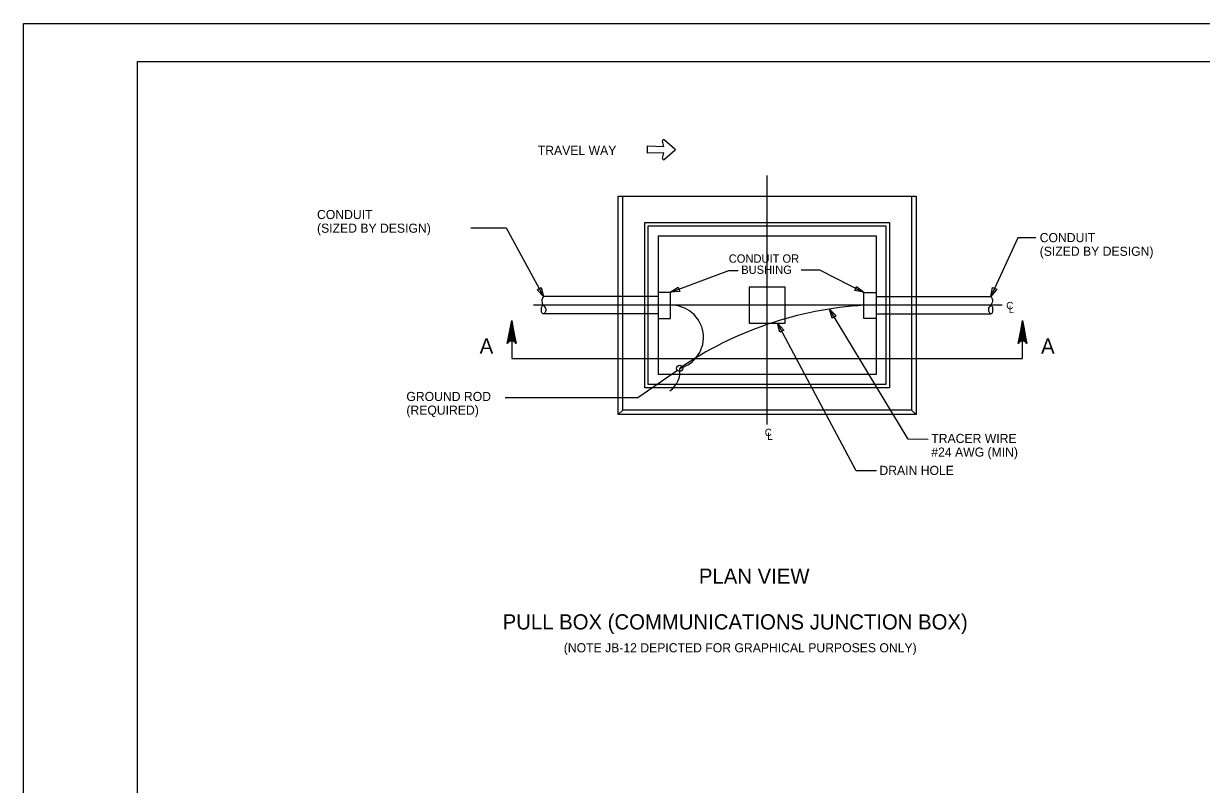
# Model space of a CAD drawing. Extents: x 1299104.8 to 1299141.6, y 239639.8 to 239661.8.
# Drawn here: x 1299104.8 to 1299120.31, y 239651.78 to 239661.8 of the extents above; entities that cross this region are included whole.
import ezdxf

# ---------------------------------------------------------------- set-up
doc = ezdxf.new("R2010")
doc.units = 0
for name, color, linetype in [('DIM TXT', 7, 'Continuous'), ('GS_plotshape_p', 7, 'Continuous'), ('Level 1', 7, 'Continuous'), ('PDF4_Geometry', 7, 'Continuous'), ('PDF4_Solid Fills', 7, 'Continuous')]:
    doc.layers.add(name, color=color, linetype=linetype)

msp = doc.modelspace()

# ---------------------------------------------------------------- linework, layer by layer
at = {"layer": 'DIM TXT'}
for p, q in [((1299113.015, 239660.092), (1299113.015, 239660.188)), ((1299113.015, 239660.188), (1299113.232, 239660.181)), ((1299113.232, 239660.181), (1299113.213, 239660.253)), ((1299113.213, 239660.253), (1299113.213, 239660.253)), ((1299113.238, 239660.269), (1299113.377, 239660.152)), ((1299113.232, 239660.099), (1299113.015, 239660.092)), ((1299113.213, 239660.027), (1299113.232, 239660.099)), ((1299113.377, 239660.128), (1299113.238, 239660.011)), ((1299114.59, 239656.519), (1299114.59, 239659.799)), ((1299112.63, 239656.65), (1299112.63, 239659.529)), ((1299112.63, 239659.529), (1299116.55, 239659.529)), ((1299116.55, 239659.529), (1299116.55, 239656.65)), ((1299112.981, 239657.001), (1299112.981, 239659.178)), ((1299112.981, 239659.178), (1299116.199, 239659.178)), ((1299113.023, 239657.045), (1299113.023, 239659.134)), ((1299113.023, 239659.134), (1299116.153, 239659.134)), ((1299116.153, 239659.134), (1299116.153, 239657.045)), ((1299116.199, 239659.178), (1299116.199, 239657.001)), ((1299113.156, 239659.003), (1299116.024, 239659.003)), ((1299113.156, 239659.003), (1299113.156, 239657.176)), ((1299116.024, 239659.003), (1299116.024, 239657.176)), ((1299114.08, 239658.545), (1299113.316, 239658.257)), ((1299114.208, 239658.545), (1299114.08, 239658.545)), ((1299115.286, 239658.551), (1299115.038, 239658.551)), ((1299115.286, 239658.551), (1299115.865, 239658.257)), ((1299112.63, 239658.203), (1299111.645, 239658.203)), ((1299113.156, 239658.203), (1299112.63, 239658.203)), ((1299113.316, 239658.257), (1299113.156, 239658.257)), ((1299113.316, 239657.917), (1299113.316, 239658.257)), ((1299115.865, 239658.257), (1299116.024, 239658.257)), ((1299115.865, 239657.917), (1299115.865, 239658.257)), ((1299116.024, 239658.203), (1299116.55, 239658.203)), ((1299116.55, 239658.203), (1299117.535, 239658.203)), ((1299117.686, 239658.089), (1299111.513, 239658.089)), ((1299112.63, 239657.976), (1299111.645, 239657.976)), ((1299113.156, 239657.976), (1299112.63, 239657.976)), ((1299116.445, 239656.324), (1299115.41, 239658.04)), ((1299116.024, 239657.976), (1299116.55, 239657.976)), ((1299116.55, 239657.976), (1299117.535, 239657.976)), ((1299113.156, 239657.917), (1299113.316, 239657.917)), ((1299115.762, 239655.908), (1299114.727, 239657.855)), ((1299116.024, 239657.917), (1299115.865, 239657.917)), ((1299115.895, 239657.259), (1299115.894, 239657.26)), ((1299116.153, 239657.045), (1299113.023, 239657.045)), ((1299116.199, 239657.001), (1299112.981, 239657.001)), ((1299112.689, 239656.709), (1299112.63, 239656.65)), ((1299116.55, 239656.65), (1299112.63, 239656.65)), ((1299116.133, 239656.709), (1299112.689, 239656.709)), ((1299116.492, 239656.709), (1299116.133, 239656.709)), ((1299116.492, 239656.709), (1299116.55, 239656.65)), ((1299116.712, 239656.323), (1299116.445, 239656.324)), ((1299116.029, 239655.907), (1299115.762, 239655.908))]:
    msp.add_line(p, q, dxfattribs=at)
for points in [[(1299112.689, 239656.709), (1299112.689, 239659.529)], [(1299116.492, 239659.529), (1299116.492, 239656.709)], [(1299110.689, 239659.111), (1299111.156, 239659.111), (1299111.645, 239658.203)], [(1299118.129, 239658.979), (1299117.889, 239658.979), (1299117.535, 239658.203)], [(1299111.142, 239656.876), (1299112.886, 239656.876), (1299113.408, 239657.233)], [(1299116.024, 239657.176), (1299113.156, 239657.176)]]:
    msp.add_lwpolyline(points, dxfattribs=at)
for points in [[(1299111.614, 239658.323), (1299111.645, 239658.203), (1299111.561, 239658.293)], [(1299113.439, 239658.269), (1299113.315, 239658.26), (1299113.42, 239658.326)], [(1299114.827, 239657.853), (1299114.827, 239658.326), (1299114.354, 239658.326), (1299114.354, 239657.853)], [(1299115.768, 239658.337), (1299115.864, 239658.26), (1299115.743, 239658.283)], [(1299117.612, 239658.3), (1299117.535, 239658.203), (1299117.557, 239658.325)], [(1299115.446, 239657.921), (1299115.41, 239658.04), (1299115.498, 239657.952)], [(1299114.758, 239657.734), (1299114.727, 239657.854), (1299114.811, 239657.763)]]:
    msp.add_lwpolyline(points, close=True, dxfattribs=at)
msp.add_circle((1299113.439, 239657.259), 0.04, dxfattribs=at)
for centre, radius, start, end in [((1299113.228, 239660.257), 0.0156, 49.7998, 194.7568), ((1299113.367, 239660.14), 0.0156, 310.2002, 49.7998), ((1299113.228, 239660.023), 0.0156, 165.2432, 310.2002), ((1299113.329, 239657.667), 0.423, 285.0795, 91.7978), ((1299116.155, 239653.284), 4.814, 93.4517, 124.3413), ((1299113.137, 239657.214), 0.305, 304.2503, 8.2882)]:
    msp.add_arc(centre, radius, start, end, dxfattribs=at)
for points in [[(1299111.645, 239658.203), (1299111.624, 239658.161), (1299111.627, 239658.128), (1299111.645, 239658.092), (1299111.677, 239658.035), (1299111.671, 239658.007), (1299111.664, 239657.988), (1299111.645, 239657.976)], [(1299117.535, 239658.203), (1299117.557, 239658.161), (1299117.553, 239658.128), (1299117.535, 239658.092), (1299117.503, 239658.035), (1299117.51, 239658.007), (1299117.516, 239657.988), (1299117.535, 239657.976)], [(1299111.645, 239657.976), (1299111.627, 239657.984), (1299111.62, 239658.002), (1299111.618, 239658.027), (1299111.62, 239658.051), (1299111.624, 239658.067), (1299111.633, 239658.082), (1299111.637, 239658.088), (1299111.643, 239658.09)], [(1299117.535, 239657.976), (1299117.553, 239657.984), (1299117.561, 239658.002), (1299117.563, 239658.027), (1299117.561, 239658.051), (1299117.557, 239658.067), (1299117.547, 239658.082), (1299117.543, 239658.088), (1299117.537, 239658.09)]]:
    msp.add_spline(points, degree=3, dxfattribs=at)
at = {"layer": 'GS_plotshape_p'}
msp.add_lwpolyline([(1299104.802, 239661.801), (1299138.802, 239661.801), (1299138.802, 239639.801), (1299104.802, 239639.801)], close=True, dxfattribs=at)
at = {"layer": 'Level 1'}
msp.add_lwpolyline([(1299138.302, 239640.301), (1299106.302, 239640.301), (1299106.302, 239661.301), (1299138.302, 239661.301)], close=True, dxfattribs=at)
at = {"layer": 'PDF4_Geometry'}
for points in [[(1299111.228, 239657.89), (1299111.17, 239657.584), (1299111.185, 239657.608), (1299111.206, 239657.62), (1299111.228, 239657.623), (1299111.248, 239657.62), (1299111.268, 239657.608), (1299111.285, 239657.584)], [(1299117.953, 239657.89), (1299117.895, 239657.584), (1299117.911, 239657.608), (1299117.933, 239657.62), (1299117.953, 239657.623), (1299117.973, 239657.62), (1299117.993, 239657.608), (1299118.01, 239657.584)]]:
    msp.add_lwpolyline(points, close=True, dxfattribs=at)
msp.add_lwpolyline([(1299111.228, 239657.89), (1299111.228, 239657.39), (1299114.59, 239657.39), (1299117.953, 239657.39), (1299117.953, 239657.89)], dxfattribs=at)
at = {"layer": 'PDF4_Solid Fills'}
for p, q in [((1299111.206, 239657.78), (1299111.228, 239657.89)), ((1299111.228, 239657.89), (1299111.228, 239657.623)), ((1299111.228, 239657.89), (1299111.248, 239657.62)), ((1299111.228, 239657.623), (1299111.228, 239657.89)), ((1299111.248, 239657.62), (1299111.228, 239657.89)), ((1299111.228, 239657.89), (1299111.248, 239657.78)), ((1299117.933, 239657.78), (1299117.953, 239657.89)), ((1299117.953, 239657.89), (1299117.953, 239657.623)), ((1299117.953, 239657.89), (1299117.973, 239657.62)), ((1299117.953, 239657.623), (1299117.953, 239657.89)), ((1299117.973, 239657.62), (1299117.953, 239657.89)), ((1299117.953, 239657.89), (1299117.973, 239657.78)), ((1299111.17, 239657.584), (1299111.185, 239657.67)), ((1299111.185, 239657.67), (1299111.206, 239657.78)), ((1299111.206, 239657.62), (1299111.185, 239657.67)), ((1299111.185, 239657.67), (1299111.185, 239657.608)), ((1299111.185, 239657.608), (1299111.185, 239657.67)), ((1299111.185, 239657.67), (1299111.206, 239657.62)), ((1299111.206, 239657.78), (1299111.206, 239657.62)), ((1299111.206, 239657.78), (1299111.228, 239657.623)), ((1299111.206, 239657.62), (1299111.206, 239657.78)), ((1299111.228, 239657.623), (1299111.206, 239657.78)), ((1299111.248, 239657.78), (1299111.248, 239657.62)), ((1299111.248, 239657.78), (1299111.268, 239657.608)), ((1299111.248, 239657.62), (1299111.248, 239657.78)), ((1299111.268, 239657.608), (1299111.248, 239657.78)), ((1299111.248, 239657.78), (1299111.268, 239657.67)), ((1299111.268, 239657.67), (1299111.268, 239657.608)), ((1299111.268, 239657.67), (1299111.285, 239657.584)), ((1299111.268, 239657.608), (1299111.268, 239657.67)), ((1299117.895, 239657.584), (1299117.911, 239657.67)), ((1299117.911, 239657.67), (1299117.933, 239657.78)), ((1299117.933, 239657.62), (1299117.911, 239657.67)), ((1299117.911, 239657.67), (1299117.911, 239657.608)), ((1299117.911, 239657.608), (1299117.911, 239657.67)), ((1299117.911, 239657.67), (1299117.933, 239657.62)), ((1299117.933, 239657.78), (1299117.933, 239657.62)), ((1299117.933, 239657.78), (1299117.953, 239657.623)), ((1299117.933, 239657.62), (1299117.933, 239657.78)), ((1299117.953, 239657.623), (1299117.933, 239657.78)), ((1299117.973, 239657.78), (1299117.993, 239657.608)), ((1299117.973, 239657.62), (1299117.973, 239657.78)), ((1299117.993, 239657.608), (1299117.973, 239657.78)), ((1299117.973, 239657.78), (1299117.993, 239657.67)), ((1299117.973, 239657.78), (1299117.973, 239657.62)), ((1299117.993, 239657.67), (1299117.993, 239657.608)), ((1299117.993, 239657.67), (1299118.01, 239657.584)), ((1299117.993, 239657.608), (1299117.993, 239657.67)), ((1299111.185, 239657.608), (1299111.17, 239657.584)), ((1299111.206, 239657.62), (1299111.185, 239657.608)), ((1299111.228, 239657.623), (1299111.206, 239657.62)), ((1299111.248, 239657.62), (1299111.228, 239657.623)), ((1299111.268, 239657.608), (1299111.248, 239657.62)), ((1299111.285, 239657.584), (1299111.268, 239657.608)), ((1299117.911, 239657.608), (1299117.895, 239657.584)), ((1299117.933, 239657.62), (1299117.911, 239657.608)), ((1299117.953, 239657.623), (1299117.933, 239657.62)), ((1299117.973, 239657.62), (1299117.953, 239657.623)), ((1299117.993, 239657.608), (1299117.973, 239657.62)), ((1299118.01, 239657.584), (1299117.993, 239657.608))]:
    msp.add_line(p, q, dxfattribs=at)

# ---------------------------------------------------------------- texts
at = {"layer": 'DIM TXT'}
for s, height, p in [('TRAVEL WAY', 0.12, (1299111.571, 239660.071)), ('CONDUIT ', 0.12, (1299108.665, 239659.225)), ('(SIZED BY DESIGN)', 0.12, (1299108.665, 239659.045)), ('CONDUIT ', 0.12, (1299118.178, 239658.921)), ('CONDUIT OR', 0.1094, (1299114.085, 239658.65)), ('(SIZED BY DESIGN)', 0.12, (1299118.178, 239658.741)), ('BUSHING', 0.1094, (1299114.249, 239658.503)), ('C', 0.096, (1299117.738, 239658.038)), ('L', 0.096, (1299117.77, 239657.987)), ('A', 0.2, (1299110.806, 239657.453)), ('A', 0.2, (1299118.196, 239657.452)), ('GROUND ROD', 0.12, (1299109.841, 239656.828)), ('(REQUIRED)', 0.12, (1299109.841, 239656.648)), ('C', 0.096, (1299114.558, 239656.366)), ('L', 0.096, (1299114.59, 239656.316)), ('TRACER WIRE', 0.12, (1299116.751, 239656.275)), ('#24 AWG (MIN)', 0.12, (1299116.751, 239656.095)), ('DRAIN HOLE', 0.12, (1299116.068, 239655.854)), ('PLAN VIEW', 0.2, (1299113.692, 239654.421)), ('PULL BOX (COMMUNICATIONS JUNCTION BOX)', 0.2, (1299111.109, 239653.818)), ('(NOTE JB-12 DEPICTED FOR GRAPHICAL PURPOSES ONLY)', 0.12, (1299111.913, 239653.517))]:
    msp.add_text(s, height=height, dxfattribs=at).set_placement(p)

doc.saveas('drawing.dxf')
